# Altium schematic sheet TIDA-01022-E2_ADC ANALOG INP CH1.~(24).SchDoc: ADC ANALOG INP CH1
size 431 x 279 mm; Date: Not shown in title block; ApprovedBy: Not shown in title block; CheckedBy: Not shown in title block; Author: Not shown in title block; CompanyName: Not shown in title block; DrawnBy: Avinash N; Engineer: Not shown in title block; Organization: Not shown in title block; Address1: Not shown in title block; Address2: Not shown in title block; Address3: Not shown in title block; Address4: Not shown in title block; DocumentNumber: 1; Revision: Use project parameter SCH_Rev; SheetNumber: 2; SheetTotal: 26; PageSetup: Record=PageOptions¦CenterHorizontal=True¦CenterVertical=True¦PrintScale=1.00¦XCorrection=1.00¦YCorrection=1.00¦PrintKind=0¦BorderSize=5000000¦LeftOffset=0¦BottomOffset=0¦Orientation=2¦PaperLength=1000¦PaperWidth=1000¦Scale=100¦PaperSource=15¦PrintQuality=600¦MediaType=1¦DitherType=10¦PaperKind=Letter¦PrintScaleMode=1
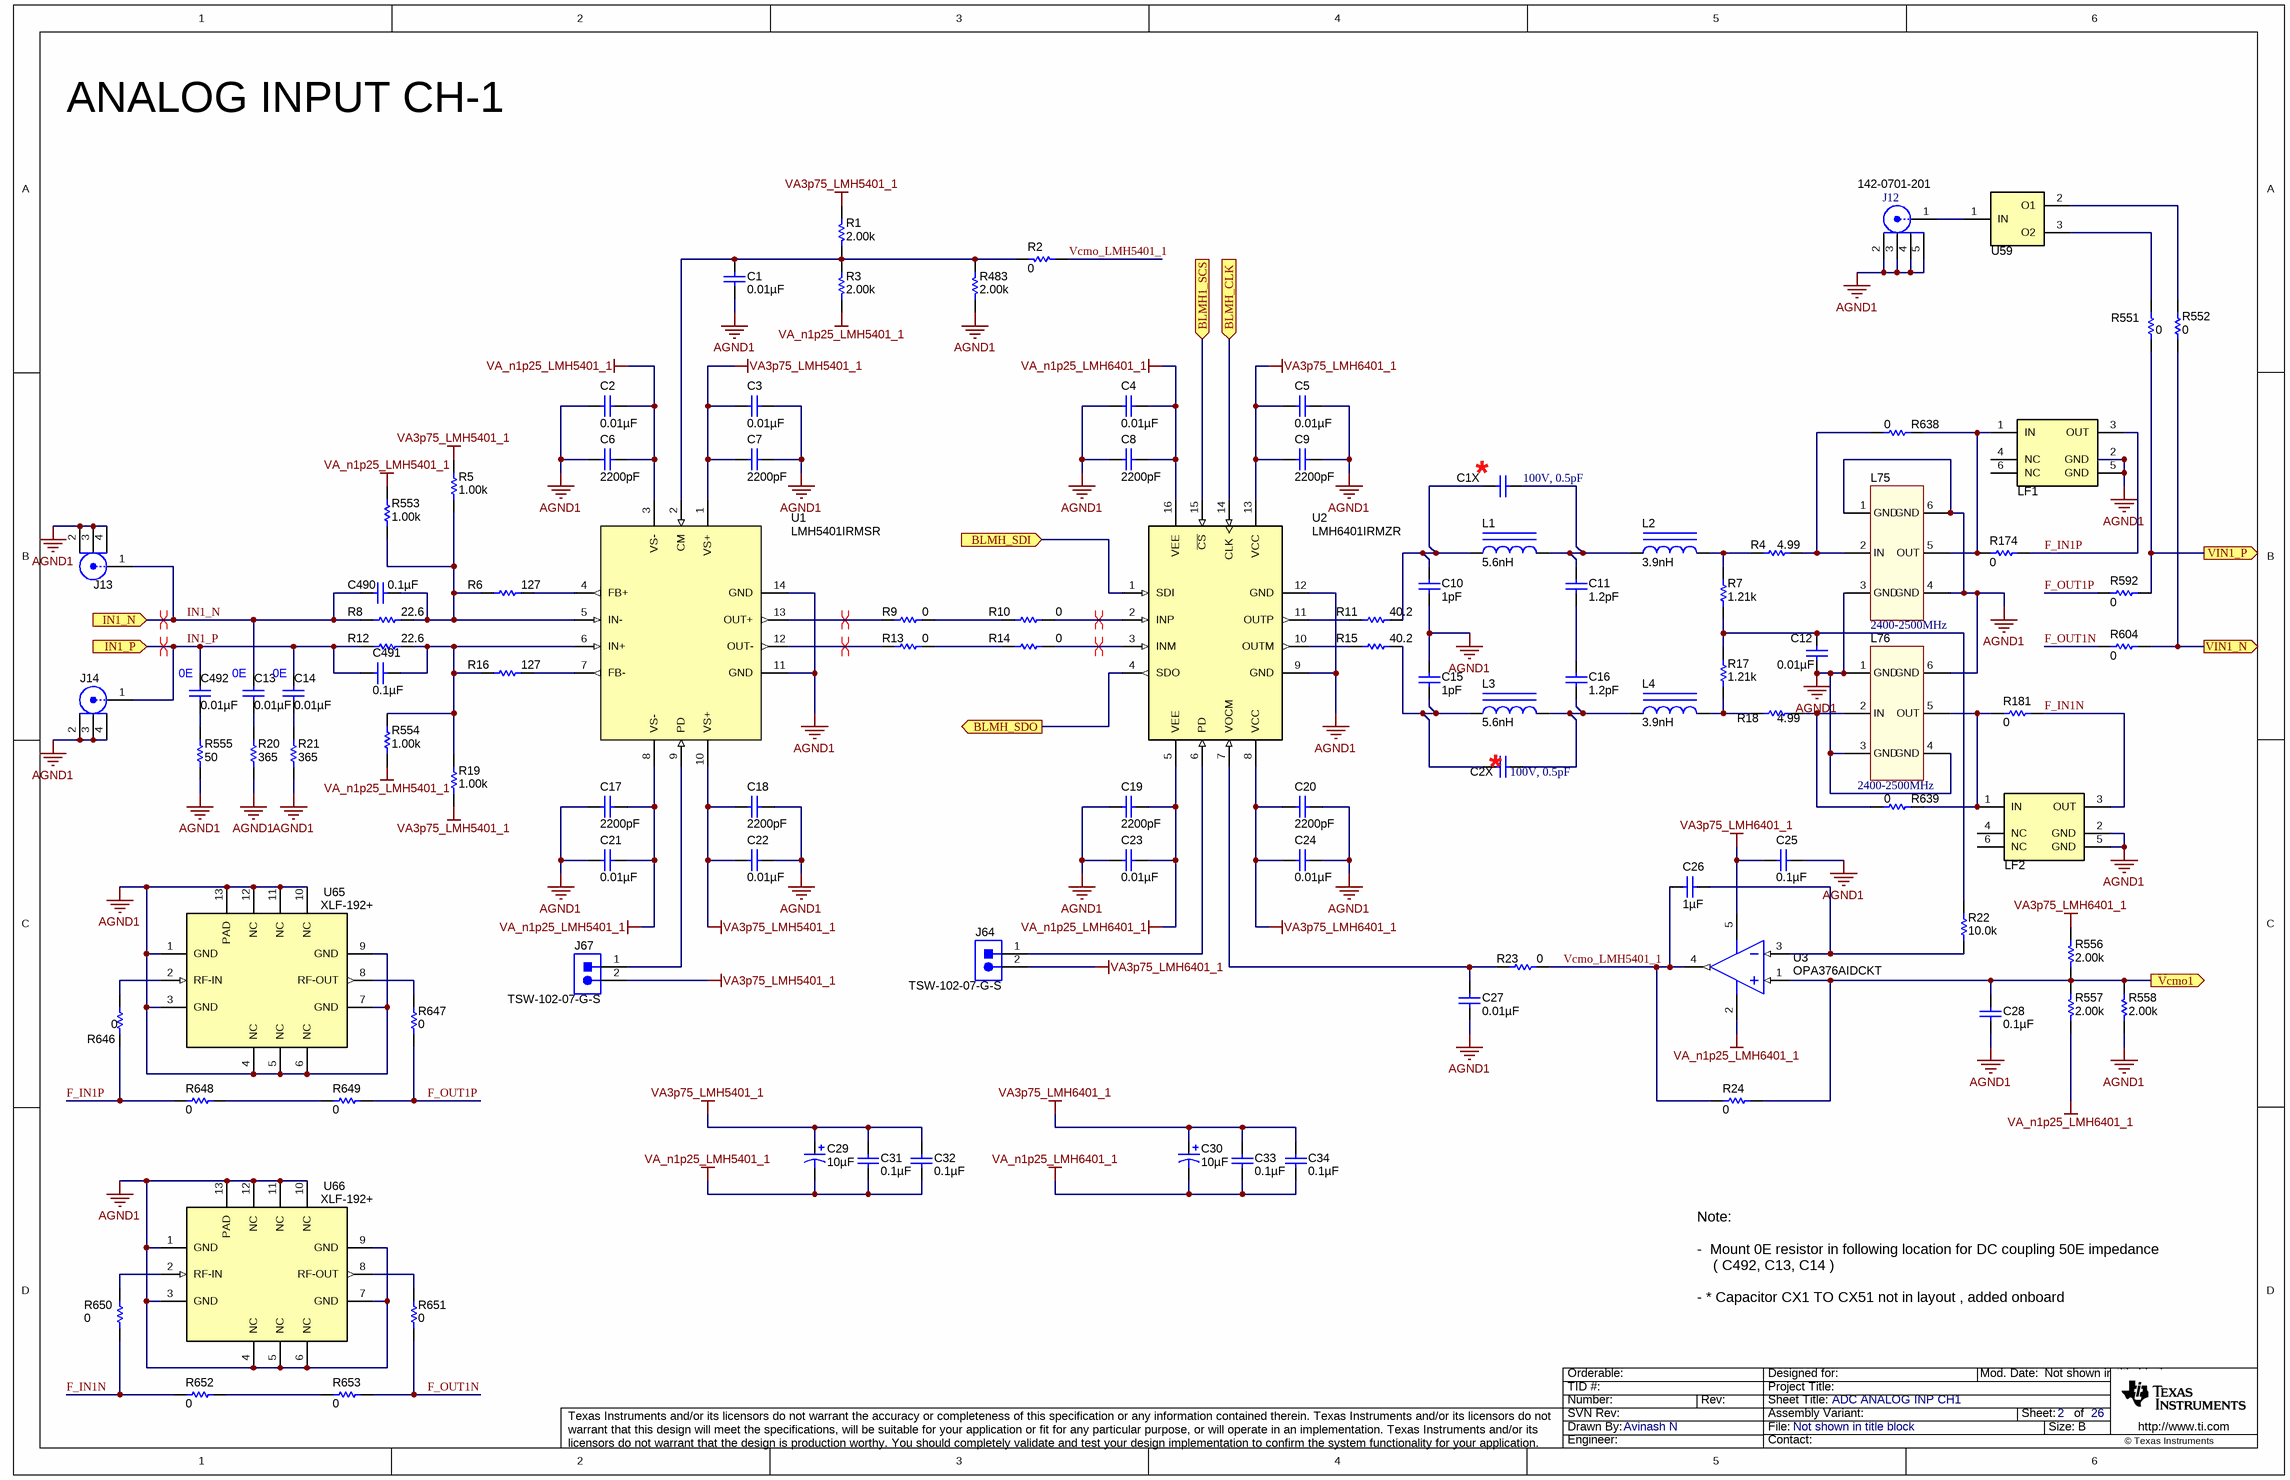
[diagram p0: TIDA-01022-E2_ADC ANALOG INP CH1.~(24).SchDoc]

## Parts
C1  ValueDisplayed: 0.01µF  [0402]  (hidden comment: GRM155R71E103KA01D)
C1X  100V, 0.5pF  [0603_1.6x0.8x0.8mm_Reflow Soldering]
C2  ValueDisplayed: 0.01µF  [0306]  (hidden comment: LLL185R71E103MA01L)
C2X  100V, 0.5pF  [0603_1.6x0.8x0.8mm_Reflow Soldering]
C3  ValueDisplayed: 0.01µF  [0306]  (hidden comment: LLL185R71E103MA01L)
C4  ValueDisplayed: 0.01µF  [0306]  (hidden comment: LLL185R71E103MA01L)
C5  ValueDisplayed: 0.01µF  [0306]  (hidden comment: LLL185R71E103MA01L)
C6  ValueDisplayed: 2200pF  [0306]  (hidden comment: LLL185R71H222MA01L)
C7  ValueDisplayed: 2200pF  [0306]  (hidden comment: LLL185R71H222MA01L)
C8  ValueDisplayed: 2200pF  [0306]  (hidden comment: LLL185R71H222MA01L)
C9  ValueDisplayed: 2200pF  [0306]  (hidden comment: LLL185R71H222MA01L)
C10  ValueDisplayed: 1pF  [0402]  (hidden comment: GRM1555C1H1R0CA01D)
C11  ValueDisplayed: 1.2pF  [0402]  (hidden comment: GRM1555C1H1R2BA01D)
C12  ValueDisplayed: 0.01µF  [0402]  (hidden comment: GRM155R71E103KA01D)
C13  ValueDisplayed: 0.01µF  [0402]  (hidden comment: GRM155R71E103KA01D)
C14  ValueDisplayed: 0.01µF  [0402]  (hidden comment: GRM155R71E103KA01D)
C15  ValueDisplayed: 1pF  [0402]  (hidden comment: GRM1555C1H1R0CA01D)
C16  ValueDisplayed: 1.2pF  [0402]  (hidden comment: GRM1555C1H1R2BA01D)
C17  ValueDisplayed: 2200pF  [0306]  (hidden comment: LLL185R71H222MA01L)
C18  ValueDisplayed: 2200pF  [0306]  (hidden comment: LLL185R71H222MA01L)
C19  ValueDisplayed: 2200pF  [0306]  (hidden comment: LLL185R71H222MA01L)
C20  ValueDisplayed: 2200pF  [0306]  (hidden comment: LLL185R71H222MA01L)
C21  ValueDisplayed: 0.01µF  [0306]  (hidden comment: LLL185R71E103MA01L)
C22  ValueDisplayed: 0.01µF  [0306]  (hidden comment: LLL185R71E103MA01L)
C23  ValueDisplayed: 0.01µF  [0306]  (hidden comment: LLL185R71E103MA01L)
C24  ValueDisplayed: 0.01µF  [0306]  (hidden comment: LLL185R71E103MA01L)
C25  ValueDisplayed: 0.1µF  [0402]  (hidden comment: C1005X5R1A104K050BA)
C26  ValueDisplayed: 1µF  [0603]  (hidden comment: C1608X5R1A105K080AC)
C27  ValueDisplayed: 0.01µF  [0402]  (hidden comment: GRM155R71E103KA01D)
C28  ValueDisplayed: 0.1µF  [0402]  (hidden comment: C1005X5R1A104K050BA)
C29  ValueDisplayed: 10µF  [3216-18]  (hidden comment: TPSA106K010R0900)
C30  ValueDisplayed: 10µF  [3216-18]  (hidden comment: TPSA106K010R0900)
C31  ValueDisplayed: 0.1µF  [0402]  (hidden comment: C1005X5R1A104K050BA)
C32  ValueDisplayed: 0.1µF  [0402]  (hidden comment: C1005X5R1A104K050BA)
C33  ValueDisplayed: 0.1µF  [0402]  (hidden comment: C1005X5R1A104K050BA)
C34  ValueDisplayed: 0.1µF  [0402]  (hidden comment: C1005X5R1A104K050BA)
C490  ValueDisplayed: 0.1µF  [0402]  (hidden comment: GRM155R71C104JA88D)
C491  ValueDisplayed: 0.1µF  [0402]  (hidden comment: GRM155R71C104JA88D)
C492  ValueDisplayed: 0.01µF  [0402]  (hidden comment: GRM155R71E103KA01D)
J12  142-0701-201  [Johnson_142-0701-20x]
J13  142-0771-831  [Johnson_142-0771-831]  (value not drawn)
J14  142-0771-831  [Johnson_142-0771-831]  (value not drawn)
J64  TSW-102-07-G-S  [TSW-102-07-G-S]
J67  TSW-102-07-G-S  [TSW-102-07-G-S]
L1  ValueDisplayed: 5.6nH  [LQW18A]  (hidden comment: LQW18AN5N6D10D)
L2  ValueDisplayed: 3.9nH  [0603HC]  (hidden comment: 0603HC-3N9XJLU)
L3  ValueDisplayed: 5.6nH  [LQW18A]  (hidden comment: LQW18AN5N6D10D)
L4  ValueDisplayed: 3.9nH  [0603HC]  (hidden comment: 0603HC-3N9XJLU)
L75  value 2400-2500MHz  [WE-LPF_0603]  (hidden comment: WE-LPF, 748112024)
L76  value 2400-2500MHz  [WE-LPF_0603]  (hidden comment: WE-LPF, 748112024)
LF1  LFL182G45TC3B746  [FIL_LFL18_TC1]  (value not drawn)
LF2  LFL182G45TC3B746  [FIL_LFL18_TC1]  (value not drawn)
R1  ValueDisplayed: 2.00k  [0402]  (hidden comment: CRCW04022K00FKED)
R2  ValueDisplayed: 0  [0402]  (hidden comment: CRCW04020000Z0ED)
R3  ValueDisplayed: 2.00k  [0402]  (hidden comment: CRCW04022K00FKED)
R4  ValueDisplayed: 4.99  [0402]  (hidden comment: CRCW04024R99FKED)
R5  ValueDisplayed: 1.00k  [0402]  (hidden comment: ERJ-2RKF1001X)
R6  ValueDisplayed: 127  [0402]  (hidden comment: CRCW0402127RFKED)
R7  ValueDisplayed: 1.21k  [0402]  (hidden comment: CRCW04021K21FKED)
R8  ValueDisplayed: 22.6  [0402]  (hidden comment: CRCW040222R6FKED)
R9  ValueDisplayed: 0  [0402]  (hidden comment: CRCW04020000Z0ED)
R10  ValueDisplayed: 0  [0402]  (hidden comment: CRCW04020000Z0ED)
R11  ValueDisplayed: 40.2  [0402]  (hidden comment: CRCW040240R2FKED)
R12  ValueDisplayed: 22.6  [0402]  (hidden comment: CRCW040222R6FKED)
R13  ValueDisplayed: 0  [0402]  (hidden comment: CRCW04020000Z0ED)
R14  ValueDisplayed: 0  [0402]  (hidden comment: CRCW04020000Z0ED)
R15  ValueDisplayed: 40.2  [0402]  (hidden comment: CRCW040240R2FKED)
R16  ValueDisplayed: 127  [0402]  (hidden comment: CRCW0402127RFKED)
R17  ValueDisplayed: 1.21k  [0402]  (hidden comment: CRCW04021K21FKED)
R18  ValueDisplayed: 4.99  [0402]  (hidden comment: CRCW04024R99FKED)
R19  ValueDisplayed: 1.00k  [0402]  (hidden comment: ERJ-2RKF1001X)
R20  ValueDisplayed: 365  [0402]  (hidden comment: CRCW0402365RFKED)
R21  ValueDisplayed: 365  [0402]  (hidden comment: CRCW0402365RFKED)
R22  ValueDisplayed: 10.0k  [0402]  (hidden comment: CRCW040210K0FKED)
R23  ValueDisplayed: 0  [0402]  (hidden comment: CRCW04020000Z0ED)
R24  ValueDisplayed: 0  [0402]  (hidden comment: CRCW04020000Z0ED)
R174  ValueDisplayed: 0  [0402_FILTER]  (hidden comment: CRCW04020000Z0ED)
R181  ValueDisplayed: 0  [0402_FILTER]  (hidden comment: CRCW04020000Z0ED)
R483  ValueDisplayed: 2.00k  [0402]  (hidden comment: CRCW04022K00FKED)
R551  ValueDisplayed: 0  [0201_adc]  (hidden comment: CRCW02010000Z0ED)
R552  ValueDisplayed: 0  [0201_adc]  (hidden comment: CRCW02010000Z0ED)
R553  ValueDisplayed: 1.00k  [0402]  (hidden comment: ERJ-2RKF1001X)
R554  ValueDisplayed: 1.00k  [0402]  (hidden comment: ERJ-2RKF1001X)
R555  ValueDisplayed: 50  [0402]  (hidden comment: FC0402E50R0BTBST1)
R556  ValueDisplayed: 2.00k  [0402]  (hidden comment: CRCW04022K00FKED)
R557  ValueDisplayed: 2.00k  [0402]  (hidden comment: CRCW04022K00FKED)
R558  ValueDisplayed: 2.00k  [0402]  (hidden comment: CRCW04022K00FKED)
R592  ValueDisplayed: 0  [0201_adc]  (hidden comment: CRCW02010000Z0ED)
R604  ValueDisplayed: 0  [0201_adc]  (hidden comment: CRCW02010000Z0ED)
R638  ValueDisplayed: 0  [0402_FILTER]  (hidden comment: CRCW04020000Z0ED)
R639  ValueDisplayed: 0  [0402_FILTER]  (hidden comment: CRCW04020000Z0ED)
R646  ValueDisplayed: 0  [0201_adc]  (hidden comment: CRCW02010000Z0ED)
R647  ValueDisplayed: 0  [0201_adc]  (hidden comment: CRCW02010000Z0ED)
R648  ValueDisplayed: 0  [0201_adc]  (hidden comment: CRCW02010000Z0ED)
R649  ValueDisplayed: 0  [0201_adc]  (hidden comment: CRCW02010000Z0ED)
R650  ValueDisplayed: 0  [0201_adc]  (hidden comment: CRCW02010000Z0ED)
R651  ValueDisplayed: 0  [0201_adc]  (hidden comment: CRCW02010000Z0ED)
R652  ValueDisplayed: 0  [0201_adc]  (hidden comment: CRCW02010000Z0ED)
R653  ValueDisplayed: 0  [0201_adc]  (hidden comment: CRCW02010000Z0ED)
U1  LMH5401IRMSR  [RMS0014A]
U2  LMH6401IRMZR  [RMZ0016A]
U3  OPA376AIDCKT  [DCK0005A_N]
U59  BAL-0006SMG  [Marki_BAL-0006SMG]  (value not drawn)
U65  XLF-192+  [DQ1225]
U66  XLF-192+  [DQ1225]

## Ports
BLMH1_SCS (in), BLMH_CLK (in), BLMH_SDI (in), BLMH_SDO (out), IN1_N (in), IN1_P (in), Vcmo1 (out), VIN1_N (out), VIN1_P (out)

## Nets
AGND1: C1.2 C2.1 C3.1 C4.1 C5.1 C6.2 C7.2 C8.2 C9.2 C10.2 C12.2 C15.2 C17.2 C18.2 C19.2 C20.2 C21.1 C22.1 C23.1 C24.1 C25.1 C27.2 C28.2 J12.2 J12.3 J12.4 J12.5 J13.2 J13.3 J13.4 J14.2 J14.3 J14.4 L75.1(GND) L75.3(GND) L75.4(GND) L75.6(GND) L76.1(GND) L76.3(GND) L76.4(GND) L76.6(GND) LF1.2(GND) LF1.5(GND) LF2.2(GND) LF2.5(GND) R20.1 R21.1 R483.1 R555.1 R558.1 U1.11(GND) U1.14(GND) U2.9(GND) U2.12(GND) U65.1(GND) U65.3(GND) U65.4(NC) U65.5(NC) U65.6(NC) U65.7(GND) U65.9(GND) U65.10(NC) U65.11(NC) U65.12(NC) U65.13(PAD) U66.1(GND) U66.3(GND) U66.4(NC) U66.5(NC) U66.6(NC) U66.7(GND) U66.9(GND) U66.10(NC) U66.11(NC) U66.12(NC) U66.13(PAD)
VA3p75_LMH5401_1: C3.2 C7.1 C18.1 C22.2 C29.1(+) C31.1 C32.1 J67.2 R1.2 R5.2 R19.1 U1.1(VS+) U1.10(VS+)
VA3p75_LMH6401_1: C5.2 C9.1 C20.1 C24.2 C25.2 C30.1(+) C33.1 C34.1 J64.2 R556.2 U2.8(VCC) U2.13(VCC) U3.5(V+)
VA_n1p25_LMH5401_1: C2.2 C6.1 C17.1 C21.2 C29.2(-) C31.2 C32.2 R3.1 R553.2 R554.2 U1.3(VS-) U1.8(VS-)
VA_n1p25_LMH6401_1: C4.2 C8.1 C19.1 C23.2 C30.2(-) C33.2 C34.2 R557.1 U2.5(VEE) U2.16(VEE) U3.2(V-)
BLMH1_SCS: U2.15(~{CS}) ; port BLMH1_SCS
BLMH_CLK: U2.14(CLK) ; port BLMH_CLK
BLMH_SDI: U2.1(SDI) ; port BLMH_SDI
BLMH_SDO: U2.4(SDO) ; port BLMH_SDO
F_IN1N: LF2.3(OUT) R181.2 R650.1 R652.1
F_IN1P: LF1.3(OUT) R174.2 R646.1 R648.1
F_OUT1N: R604.1 R651.1 R653.2
F_OUT1P: R592.1 R647.1 R649.2
IN1_N: C13.1 C490.2 J13.1 R8.1 ; port IN1_N
IN1_P: C14.1 C491.1 C492.1 J14.1 R12.1 ; port IN1_P
Vcmo1: C28.1 R24.1 R556.1 R557.2 R558.2 U3.1(IN+) ; port Vcmo1
Vcmo_LMH5401_1: C26.1 R2.2 R23.1 R24.2 U3.4(OUT)
VIN1_N: R552.2 R604.2 ; port VIN1_N
VIN1_P: R551.2 R592.2 ; port VIN1_P
NetC1_1: C1.1 R1.1 R2.1 R3.2 R483.2 U1.2(CM)
NetC1X_1: C1X.1 C10.1 L1.1 R11.1
NetC1X_2: C1X.2 C11.1 L1.2 L2.1
NetC2X_1: C2X.1 C15.1 L3.1 R15.1
NetC2X_2: C2X.2 C16.1 L3.2 L4.1
NetC11_2: C11.2 C16.2
NetC12_1: C12.1 R7.1 R17.1 R22.2
NetC13_2: C13.2 R20.2
NetC14_2: C14.2 R21.2
NetC26_2: C26.2 R22.1 U3.3(IN-)
NetC27_1: C27.1 R23.2 U2.7(VOCM)
NetC490_1: C490.1 R5.1 R6.1 R8.2 R553.1 U1.5(IN-)
NetC491_2: C491.2 R12.2 R16.1 R19.2 R554.1 U1.6(IN+)
NetC492_2: C492.2 R555.2
NetJ12_1: J12.1 U59.1(IN)
NetJ64_1: J64.1 U2.6(PD)
NetJ67_1: J67.1 U1.9(PD)
NetL2_2: L2.2 R4.1 R7.2
NetL4_2: L4.2 R17.2 R18.1
NetL75_2: L75.2(IN) R4.2 R638.1
NetL75_5: L75.5(OUT) LF1.1(IN) R174.1 R638.2
NetL76_2: L76.2(IN) R18.2 R639.1
NetL76_5: L76.5(OUT) LF2.1(IN) R181.1 R639.2
NetR6_2: R6.2 U1.4(FB+)
NetR9_1: R9.1 U1.13(OUT+)
NetR9_2: R9.2 R10.2
NetR10_1: R10.1 U2.2(INP)
NetR11_2: R11.2 U2.11(OUTP)
NetR13_1: R13.1 U1.12(OUT-)
NetR13_2: R13.2 R14.2
NetR14_1: R14.1 U2.3(INM)
NetR15_2: R15.2 U2.10(OUTM)
NetR16_2: R16.2 U1.7(FB-)
NetR551_1: R551.1 U59.3(O2)
NetR552_1: R552.1 U59.2(O1)
NetR646_2: R646.2 U65.2(RF-IN)
NetR647_2: R647.2 U65.8(RF-OUT)
NetR648_2: R648.2 R649.1
NetR650_2: R650.2 U66.2(RF-IN)
NetR651_2: R651.2 U66.8(RF-OUT)
NetR652_2: R652.2 R653.1

Not connected (* = marked no-connect by the designer): LF1 4(NC) 6(NC); LF2 4(NC) 6(NC)

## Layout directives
differential pair: IN1_N, IN1_P, NetR9_1, NetR10_1, NetR13_1, NetR14_1

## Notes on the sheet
- ANALOG INPUT CH-1
- (near C1X) *
- (near C492) 0E
- (near C13) 0E
- (near C14) 0E
- (near C2X) *
- Note:
  -  Mount 0E resistor in following location for DC coupling 50E impedance
  ( C492, C13, C14 )
  - * Capacitor CX1 TO CX51 not in layout , added onboard

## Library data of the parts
C1 C12-C14 C27 C492 = GRM155R71E103KA01D: CAP, CERM, 0.01 µF, 25 V, +/- 10%, X7R, 0402; Manufacturer: MuRata; Polarized: N; CompType: Capacitor; Value: 0.01uF; U/M: EA; Cap_F: 0.00000001; Tolerance_%: 10; Value1: Unknown; VDC_V: 25; Value2: 25V; TaMin_C: -55; TaMax_C: 125; SizeArea_mm2: 0.5; SizeAreaWB_mm2: 3; SizeX_mm: 1; SizeZ_mm: 0.6; AEC Category: Q200
C1X C2X = 885012006086: WCAP-CSGP Ceramic Capacitors, 0603, NP0, 100V, 0.5pF; Rated Voltage: 100V DC
C2-C5 C21-C24 = LLL185R71E103MA01L: CAP, CERM, 0.01 µF, 25 V, +/- 20%, X7R, 0306; Manufacturer: MuRata; Polarized: N; CompType: Capacitor; Value: 0.01uF; U/M: EA; Cap_F: 0.00000001; Tolerance_%: 20; Value1: Unknown; VDC_V: 25; Value2: 25V; TaMin_C: -55; TaMax_C: 125; SizeArea_mm2: 1.28; SizeAreaWB_mm2: 4.68; SizeX_mm: 0.8; SizeY_mm: 1.6; SizeZ_mm: 0.6; AEC Category: Q200
C6-C9 C17-C20 = LLL185R71H222MA01L: CAP, CERM, 2200 pF, 50 V, +/- 20%, X7R, 0306; Manufacturer: MuRata; Polarized: N; CompType: Capacitor; Value: 2200pF; U/M: EA; Cap_F: 0.0000000022; Tolerance_%: 20; Value1: Unknown; VDC_V: 50; Value2: 50V; TaMin_C: -55; TaMax_C: 125; SizeArea_mm2: 1.28; SizeAreaWB_mm2: 4.68; SizeX_mm: 0.8; SizeY_mm: 1.6; SizeZ_mm: 0.6; AEC Category: Q200
C10 C15 = GRM1555C1H1R0CA01D: CAP, CERM, 1 pF, 50 V, +/- 5%, C0G/NP0, 0402; Manufacturer: MuRata; Polarized: N; CompType: Capacitor; Value: 1pF; U/M: EA; Cap_F: 0.000000000001; Tolerance_%: 5; Value1: Unknown; VDC_V: 50; Value2: 50V; TaMin_C: -55; TaMax_C: 125; SizeArea_mm2: 0.5; SizeAreaWB_mm2: 3; SizeX_mm: 1; SizeZ_mm: 0.6; AEC Category: Q200
C11 C16 = GRM1555C1H1R2BA01D: CAP, CERM, 1.2 pF, 50 V, +/- 8.3%, C0G/NP0, 0402; Manufacturer: MuRata; Polarized: N; CompType: Capacitor; Value: 1.2pF; U/M: EA; Cap_F: 0.0000000000012; Tolerance_%: 8.3; Value1: Unknown; VDC_V: 50; Value2: 50V; TaMin_C: -55; TaMax_C: 125; SizeArea_mm2: 0.5; SizeAreaWB_mm2: 3; SizeX_mm: 1; SizeZ_mm: 0.6; AEC Category: Q200
C25 C28 C31-C34 = C1005X5R1A104K050BA: CAP, CERM, 0.1 µF, 10 V, +/- 10%, X5R, 0402; Manufacturer: TDK; Polarized: N; CompType: Capacitor; Value: 0.1uF; U/M: EA; Cap_F: 0.0000001; Tolerance_%: 10; Value1: Unknown; Value2: 10V; TaMin_C: -55; TaMax_C: 85; SizeArea_mm2: 0.5; SizeAreaWB_mm2: 3; SizeX_mm: 1; SizeZ_mm: 0.6; AEC Category: Q200
C26 = C1608X5R1A105K080AC: CAP, CERM, 1 µF, 10 V, +/- 10%, X5R, 0603; Manufacturer: TDK; Polarized: N; CompType: Capacitor; Value: 1uF; U/M: EA; Cap_F: 0.000001; Tolerance_%: 10; Value1: Unknown; Value2: 10V; TaMin_C: -55; TaMax_C: 85; SizeArea_mm2: 1.28; SizeAreaWB_mm2: 4.68; SizeX_mm: 1.6; SizeY_mm: 0.8; SizeZ_mm: 1; AEC Category: Q200
C29 C30 = TPSA106K010R0900: CAP, TA, 10 µF, 10 V, +/- 10%, 0.9 ohm, SMD; Manufacturer: AVX; Polarized: Y; CompType: Capacitor; Value: 10uF; U/M: EA; Cap_F: 0.00001; Tolerance_%: 10; Value1: 0.9 ohm; Value2: 10V; ESR_ohm: 0.9; IRMS_A: 0.26; TaMin_C: -55; TaMax_C: 125; Cap_Case: A; SizeAreaWB_mm2: 10.92; SizeArea_mm2: 5.12; SizeX_mm: 3.2; SizeY_mm: 1.6; SizeZ_mm: 1.8; AEC Category: Q200
C490 C491 = GRM155R71C104JA88D: CAP, CERM, 0.1 µF, 16 V, +/- 5%, X7R, 0402; Manufacturer: MuRata; Polarized: N; CompType: Capacitor; Value: 0.1uF; U/M: EA; Cap_F: 0.0000001; Tolerance_%: 5; Value1: Unknown; VDC_V: 16; Value2: 16V; TaMin_C: -55; TaMax_C: 125; SizeArea_mm2: 0.5; SizeAreaWB_mm2: 3; SizeX_mm: 1; SizeZ_mm: 0.6; AEC Category: Q200
J12 = 142-0701-201: Connector, TH, SMA; Manufacturer: Emerson Network Power; SymbolCreator: X0208326
J13 J14 = 142-0771-831: JACK, SMA, 50 Ohm, Gold, Edge Mount; Manufacturer: Johnson; SymbolCreator: Altium; Gender: Female; Voltage_V: 170
J64 J67 = TSW-102-07-G-S: Header, 100mil, 2x1, Gold, TH; Manufacturer: Samtec; SymbolCreator: a0412235; Pitch_mm: 2.54; Gender: Male; Shrouded: N; Row_Count: 1; Current_A: 6.3; Voltage_V: 550; Cert_CSA: Y
L1 L3 = LQW18AN5N6D10D: Inductor, Wirewound, 5.6 nH, 0.9 A, 0.045 ohm, SMD; Manufacturer: MuRata; Value: 5.6nH; Ind_H: 5.6E-9; Imax_A: 0.9; Irms: 0.9A @ C rise; DCR_ohm: 0.045; Value2: 0.9A; SizeAreaWB_mm2: 4.68; SizeArea_mm2: 1.28; SizeX_mm: 1.6; SizeY_mm: 0.8; SizeZ_mm: 1; AEC Category: Q200; AEC Qualified: N
L2 L4 = 0603HC-3N9XJLU: Inductor, Wirewound, Ceramic, 3.9 nH, 2.2 A, 0.054 ohm, SMD; Manufacturer: Coilcraft; Value: 3.9nH; Ind_H: 3.9E-9; Imax_A: 2.2; Irms: 2.4A @ 20C rise; DCR_ohm: 0.054; Value2: 2.2A; SizeAreaWB_mm2: 5.936; SizeArea_mm2: 2.016; SizeX_mm: 1.8; SizeY_mm: 1.12; SizeZ_mm: 1.02; AEC Category: Q200
L75 L76 = WE-LPF, 748112024: WE-LPF Multilayer Chip Low-Pass Filter, size 0603, 2400-2500MHz
LF1 LF2 = LFL182G45TC3B746: Filter for Communication Equipment, SMD; Manufacturer: MuRata; SymbolCreator: Altium; SizeAreaWB_mm2: 4.68; SizeArea_mm2: 1.28; SizeX_mm: 1.6; SizeY_mm: 0.8; SizeZ_mm: 0.7
R1 R3 R483 R556-R558 = CRCW04022K00FKED: RES, 2.00 k, 1%, 0.063 W, 0402; Manufacturer: Vishay-Dale; CompType: Resistor; Value: 2.00k; Res_ohm: 2000; Value_Code: 2k00; Tolerance_%: 1; Power_W: 0.063; Value2: 0.063W; VDC_V: 50; TempCo: 100 ppm/C; SizeArea_mm2: 0.5; SizeZ_mm: 0.6; EIA_Code: E96; U/M: EA; AEC Category: Q200
R2 R9 R10 R13 R14 R23 R24 R174 R181 R638 R639 = CRCW04020000Z0ED: RES, 0, 5%, 0.063 W, 0402; Manufacturer: Vishay-Dale; CompType: Resistor; Value: 0; Value_Code: 0000; Tolerance_%: 5; Power_W: 0.063; Value2: 0.063W; VDC_V: 50; TempCo: 200 ppm/C; SizeArea_mm2: 0.5; SizeX_mm: 1; SizeZ_mm: 0.6; EIA_Code: E24; U/M: EA; AEC Category: Q200
R4 R18 = CRCW04024R99FKED: RES, 4.99, 1%, 0.063 W, 0402; Manufacturer: Vishay-Dale; CompType: Resistor; Value: 4.99; Value_Code: 4R99; Tolerance_%: 1; Power_W: 0.063; Value2: 0.063W; VDC_V: 50; TempCo: 100 ppm/C; SizeArea_mm2: 0.5; SizeZ_mm: 0.6; EIA_Code: E96; U/M: EA; AEC Category: Q200
R5 R19 R553 R554 = ERJ-2RKF1001X: RES, 1.00 k, 1%, 0.1 W, 0402; Manufacturer: Panasonic; CompType: Resistor; Value: 1.00k; Res_ohm: 1000; Value_Code: 1k00; Tolerance_%: 1; Power_W: 0.1; Value2: 0.1W; VDC_V: 50; TempCo: 100 ppm/C; SizeArea_mm2: 0.5; SizeZ_mm: 0.6; EIA_Code: E96; U/M: EA; AEC Category: Q200
R6 R16 = CRCW0402127RFKED: RES, 127, 1%, 0.063 W, 0402; Manufacturer: Vishay-Dale; CompType: Resistor; Value: 127; Value_Code: 127R; Tolerance_%: 1; Power_W: 0.063; Value2: 0.063W; VDC_V: 50; TempCo: 100 ppm/C; SizeArea_mm2: 0.5; SizeZ_mm: 0.6; EIA_Code: E96; U/M: EA; AEC Category: Q200
R7 R17 = CRCW04021K21FKED: RES, 1.21 k, 1%, 0.063 W, 0402; Manufacturer: Vishay-Dale; CompType: Resistor; Value: 1.21k; Res_ohm: 1210; Value_Code: 1k21; Tolerance_%: 1; Power_W: 0.063; Value2: 0.063W; VDC_V: 50; TempCo: 100 ppm/C; SizeArea_mm2: 0.5; SizeZ_mm: 0.6; EIA_Code: E96; U/M: EA; AEC Category: Q200
R8 R12 = CRCW040222R6FKED: RES, 22.6, 1%, 0.063 W, 0402; Manufacturer: Vishay-Dale; CompType: Resistor; Value: 22.6; Value_Code: 22R6; Tolerance_%: 1; Power_W: 0.063; Value2: 0.063W; VDC_V: 50; TempCo: 100 ppm/C; SizeArea_mm2: 0.5; SizeZ_mm: 0.6; EIA_Code: E96; U/M: EA; AEC Category: Q200
R11 R15 = CRCW040240R2FKED: RES, 40.2, 1%, 0.063 W, 0402; Manufacturer: Vishay-Dale; CompType: Resistor; Value: 40.2; Value_Code: 40R2; Tolerance_%: 1; Power_W: 0.063; Value2: 0.063W; VDC_V: 50; TempCo: 100 ppm/C; SizeArea_mm2: 0.5; SizeZ_mm: 0.6; EIA_Code: E96; U/M: EA; AEC Category: Q200
R20 R21 = CRCW0402365RFKED: RES, 365, 1%, 0.063 W, 0402; Manufacturer: Vishay-Dale; CompType: Resistor; Value: 365; Value_Code: 365R; Tolerance_%: 1; Power_W: 0.063; Value2: 0.063W; VDC_V: 50; TempCo: 100 ppm/C; SizeArea_mm2: 0.5; SizeZ_mm: 0.6; EIA_Code: E96; U/M: EA; AEC Category: Q200
R22 = CRCW040210K0FKED: RES, 10.0 k, 1%, 0.063 W, 0402; Manufacturer: Vishay-Dale; CompType: Resistor; Value: 10.0k; Res_ohm: 10000; Value_Code: 10k0; Tolerance_%: 1; Power_W: 0.063; Value2: 0.063W; VDC_V: 50; TempCo: 100 ppm/C; SizeArea_mm2: 0.5; SizeZ_mm: 0.6; EIA_Code: E96; U/M: EA; AEC Category: Q200
R551 R552 R592 R604 R646-R653 = CRCW02010000Z0ED: RES, 0, 5%, 0.05 W, 0201; Manufacturer: Vishay-Dale; CompType: Resistor; Value: 0; Value_Code: 0000; Tolerance_%: 5; Power_W: 0.05; Value2: 0.05W; TempCo: ppm/C; SizeArea_mm2: 0.18; SizeX_mm: 0.6; SizeY_mm: 0.3; SizeZ_mm: 0.26; EIA_Code: E24; U/M: EA; AEC Category: Q200; AEC Qualified: N
R555 = FC0402E50R0BTBST1: RES, 50, 0.1%, 0.5 W, 0402; Manufacturer: Vishay Thin Film; CompType: Resistor; Value: 50; Value_Code: 50R0; Tolerance_%: 0.1; Power_W: 0.5; Value2: 0.5W; TempCo: 0.1 ppm/C; SizeX_mm: 1; SizeZ_mm: 0.6; U/M: EA; AEC Category: Q200; AEC Qualified: N
U1 = LMH5401IRMSR: 8GHz Ultra Wideband Fully Differential Amplifier, RMS0014A (UQFN-14); Alternate PartNumber: LMH5401IRMST; Manufacturer: Texas Instruments; SymbolCreator: Altium; SizeArea_mm2: 6.25; SizeAreaWB_mm2: 12.25; SizeX_mm: 2.5; SizeZ_mm: 0.6; CompType: IC; U/M: EA
U2 = LMH6401IRMZR: 4.5 GHz Ultra Wideband Digital Variable Gain Amplifier, RMZ0016A (UQFN-HR-16); Alternate PartNumber: LMH6401IRMZT; Manufacturer: Texas Instruments; SymbolCreator: Altium; SizeArea_mm2: 9; SizeAreaWB_mm2: 16; SizeX_mm: 3; SizeZ_mm: 0.65; CompType: IC; U/M: EA
U3 = OPA376AIDCKT: Precision, Low Noise, Low Iq Operational Amplifier, 2.2 to 5.5 V, -40 to 125 degC, 5-pin SOT23 (DCK0005A), Green (RoHS & no Sb/Br); Manufacturer: Texas Instruments; Alternate PartNumber: Equivalent; CMRR(Min)(dB): 76; IIB(Max)(pA): 10; Iq per channel(Max)(mA): 0.95; Number of Channels: 1; Offset Drift(Typ)(uV/C): 0.32; Slew Rate(Typ)(V/us): 2; Sub Family: Low Input Bias Current Amp (<=10pA), Low Noise Amp (<=10nV/rtHz), Low Offset Voltage Amplifier (<=500uV), Low Supply Voltage Amplifier (<=2.7V), Precision Amplifier; Total Supply Voltage(Max)(+5V is 5, +/-5V is 10): 5.5; Total Supply Voltage(Min)(+5V is 5, +/-5V is 10): 2.2; Vio (25C)(Max)(mV): 0.025; Vn at 1kHz(Typ)(nV/rtHz): 7.5
U59 = BAL-0006SMG: Broadband Balun, 500 kHz to 6 GHz; Manufacturer: Marki Microwave; SymbolCreator: Altium; SizeAreaWB_mm2: 102.6169; SizeArea_mm2: 66.0969; SizeX_mm: 8.13; SizeZ_mm: 3.94
U65 U66 = CMP-0077784-1: Reflectionless Low Pass Filter, SMD; Manufacturer: Minicircuits; SizeArea_mm2: 9; SizeAreaWB_mm2: 16; SizeY_mm: 3; SizeZ_mm: 0.89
